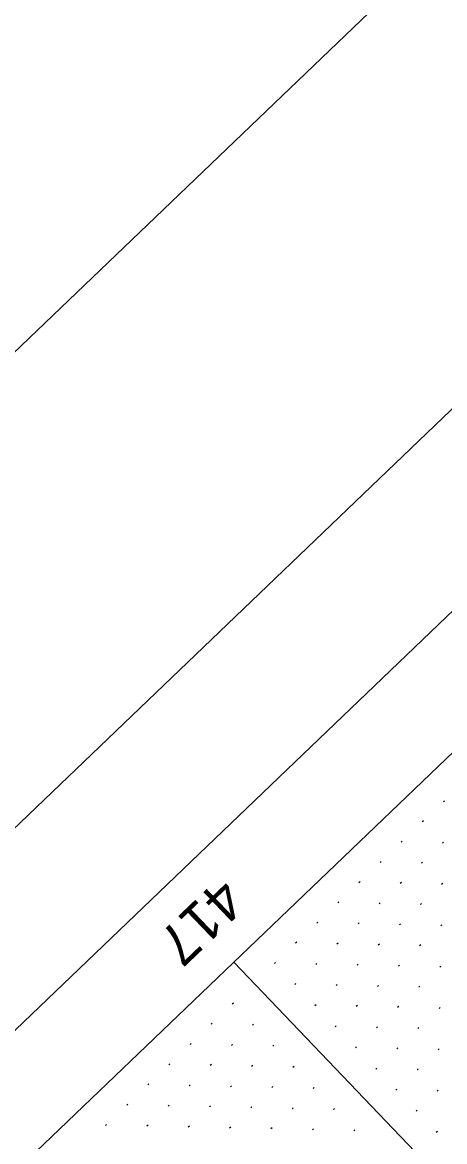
# Model space of a CAD drawing. Extents: x 2148987 to 2151117, y 142806 to 144993.
# Drawn here: x 2149297.8 to 2149370, y 143833.4 to 144024.9 of the extents above; entities that cross this region are included whole.
import ezdxf

# ---------------------------------------------------------------- set-up
doc = ezdxf.new("R2010")
doc.units = 0
for name, color, linetype in [('BASELINE', 7, 'Continuous'), ('PR_ABUT_PH3', 7, 'Continuous'), ('PR_PIER_PH3', 7, 'Continuous'), ('PR_Road_Concrete', 7, 'Continuous'), ('SHT_Profile_Grid_Minor', 7, 'Continuous'), ('Wall D Bore Txt', 7, 'Continuous')]:
    doc.layers.add(name, color=color, linetype=linetype)

msp = doc.modelspace()

# ---------------------------------------------------------------- linework, layer by layer
at = {"layer": 'BASELINE'}
msp.add_lwpolyline([(2151029.45, 144024.32), (2149802.07, 142848.08), (2149040.98, 143642.27), (2150268.36, 144818.51)], close=True, dxfattribs=at)
at = {"layer": 'PR_ABUT_PH3'}
msp.add_lwpolyline([(2151117.11, 144051.19), (2149817.52, 142805.76), (2148987.24, 143672.15), (2150286.82, 144917.58)], close=True, dxfattribs=at)
at = {"layer": 'PR_PIER_PH3'}
msp.add_line((2149333.91, 143864.13), (2149679.86, 143503.14), dxfattribs=at)
at = {"layer": 'PR_Road_Concrete'}
msp.add_line((2150227.37, 144720.36), (2149279.76, 143812.24), dxfattribs=at)
msp.add_lwpolyline([(2150941.76, 143974.91), (2149804.63, 142885.16), (2149078.13, 143643.25), (2150215.26, 144733)], close=True, dxfattribs=at)
at = {"layer": 'SHT_Profile_Grid_Minor'}
for p, q in [((2149369.95, 143891.75), (2149369.77, 143891.57)), ((2149366.34, 143888.29), (2149366.16, 143888.11)), ((2149362.73, 143884.83), (2149362.55, 143884.65)), ((2149369.8, 143884.68), (2149369.62, 143884.5)), ((2149359.12, 143881.37), (2149358.94, 143881.19)), ((2149366.19, 143881.22), (2149366.01, 143881.04)), ((2149355.51, 143877.91), (2149355.33, 143877.73)), ((2149362.58, 143877.76), (2149362.4, 143877.58)), ((2149369.65, 143877.61), (2149369.47, 143877.43)), ((2149351.9, 143874.45), (2149351.72, 143874.28)), ((2149358.97, 143874.3), (2149358.79, 143874.12)), ((2149366.04, 143874.15), (2149365.86, 143873.97)), ((2149348.29, 143870.99), (2149348.11, 143870.82)), ((2149355.36, 143870.84), (2149355.18, 143870.67)), ((2149362.43, 143870.69), (2149362.25, 143870.51)), ((2149369.5, 143870.54), (2149369.32, 143870.36)), ((2149344.68, 143867.53), (2149344.5, 143867.36)), ((2149351.75, 143867.38), (2149351.57, 143867.21)), ((2149358.82, 143867.23), (2149358.64, 143867.06)), ((2149365.89, 143867.08), (2149365.71, 143866.91)), ((2149341.07, 143864.07), (2149340.89, 143863.9)), ((2149348.14, 143863.92), (2149347.96, 143863.75)), ((2149355.21, 143863.77), (2149355.03, 143863.6)), ((2149362.28, 143863.62), (2149362.1, 143863.45)), ((2149369.35, 143863.47), (2149369.17, 143863.3)), ((2149344.53, 143860.46), (2149344.35, 143860.29)), ((2149351.6, 143860.31), (2149351.42, 143860.14)), ((2149358.67, 143860.16), (2149358.49, 143859.99)), ((2149365.74, 143860.01), (2149365.56, 143859.84)), ((2149333.85, 143857.15), (2149333.67, 143856.98)), ((2149347.99, 143856.85), (2149347.81, 143856.68)), ((2149355.06, 143856.7), (2149354.88, 143856.53)), ((2149362.13, 143856.55), (2149361.95, 143856.38)), ((2149369.2, 143856.4), (2149369.02, 143856.23)), ((2149330.24, 143853.69), (2149330.06, 143853.52)), ((2149337.31, 143853.54), (2149337.13, 143853.37)), ((2149351.45, 143853.24), (2149351.27, 143853.07)), ((2149358.52, 143853.09), (2149358.34, 143852.92)), ((2149365.59, 143852.94), (2149365.41, 143852.77)), ((2149326.63, 143850.23), (2149326.45, 143850.06)), ((2149333.7, 143850.08), (2149333.52, 143849.91)), ((2149340.77, 143849.93), (2149340.59, 143849.76)), ((2149354.91, 143849.63), (2149354.73, 143849.46)), ((2149361.98, 143849.48), (2149361.8, 143849.31)), ((2149369.05, 143849.33), (2149368.86, 143849.16)), ((2149323.02, 143846.77), (2149322.84, 143846.6)), ((2149330.09, 143846.62), (2149329.91, 143846.45)), ((2149337.16, 143846.47), (2149336.98, 143846.3)), ((2149344.23, 143846.32), (2149344.05, 143846.15)), ((2149358.37, 143846.02), (2149358.19, 143845.85)), ((2149365.44, 143845.87), (2149365.26, 143845.7)), ((2149319.41, 143843.31), (2149319.23, 143843.14)), ((2149326.48, 143843.16), (2149326.3, 143842.99)), ((2149333.55, 143843.01), (2149333.37, 143842.84)), ((2149340.62, 143842.86), (2149340.44, 143842.69)), ((2149347.69, 143842.71), (2149347.51, 143842.54)), ((2149361.83, 143842.41), (2149361.65, 143842.24)), ((2149368.9, 143842.26), (2149368.71, 143842.09)), ((2149315.8, 143839.85), (2149315.62, 143839.68)), ((2149322.87, 143839.7), (2149322.69, 143839.53)), ((2149329.94, 143839.55), (2149329.76, 143839.38)), ((2149337.01, 143839.4), (2149336.83, 143839.23)), ((2149344.08, 143839.25), (2149343.9, 143839.08)), ((2149351.15, 143839.1), (2149350.97, 143838.93)), ((2149365.29, 143838.8), (2149365.1, 143838.63)), ((2149312.19, 143836.39), (2149312.01, 143836.22)), ((2149319.26, 143836.24), (2149319.08, 143836.07)), ((2149326.33, 143836.09), (2149326.15, 143835.92)), ((2149333.4, 143835.94), (2149333.22, 143835.77)), ((2149340.47, 143835.79), (2149340.29, 143835.62)), ((2149347.54, 143835.64), (2149347.36, 143835.47)), ((2149354.61, 143835.49), (2149354.43, 143835.32)), ((2149368.74, 143835.19), (2149368.56, 143835.02))]:
    msp.add_line(p, q, dxfattribs=at)

# ---------------------------------------------------------------- texts
at = {"layer": 'Wall D Bore Txt'}
msp.add_text('417', height=7, rotation=223.7809, dxfattribs=at).set_placement((2149331.63, 143878.91))

doc.saveas('drawing.dxf')
